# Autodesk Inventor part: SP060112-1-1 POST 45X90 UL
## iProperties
Created: 2012-06
Part Number: SP060112-1-1 POST 45X90 UL
Material: Aluminum-6061
Description: PROFILE 45X90 UL
Document SubType Name: Modeling
Designer: Administrator
Stock Number: 20.1067 PROFILE 45X90 UL
Density: 2.71 g/cm^3
Mass: 4630.53 g
Surface Area: 18767.3 cm^2
Volume: 1708.68 cm^3
FINISH: CLEAR ANODIZED
Author: Administrator
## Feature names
1. Extrusion1
